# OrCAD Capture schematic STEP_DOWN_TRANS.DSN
size A
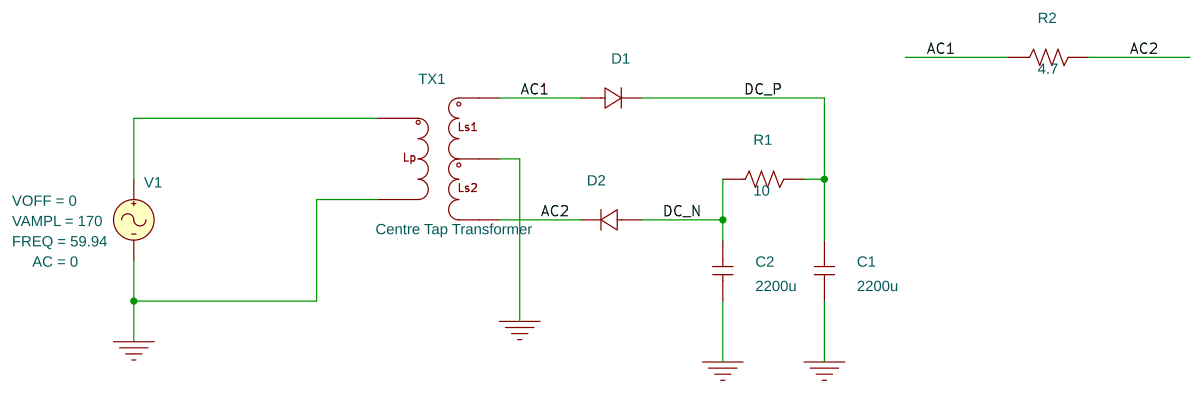
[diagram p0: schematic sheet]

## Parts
C1  2200u  [cap196]
C2  2200u  [cap196]
D1  POWER_DIODE_P
D2  POWER_DIODE_P
R1  10  [AXRC05]
R2  4.7  [AXRC05]
TX1  Centre Tap Transformer
V1  VSIN

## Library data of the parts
C1 C2 = C
D1 D2 = POWER_DIODE_P: CT_ZERO_VOLTS: 300p; I_REV_LEAK: 1e-5; VJ_KNEE: 0.9
R1 R2 = R
TX1 = CETAPS: AppProp: modelname=CETAPS_Model,LP1=1m,RP1=10m,Rs1=10m,N=0.1,LI=100n
V1 = VSIN: AC: 0; FREQ: 59.94; VAMPL: 170; VOFF: 0

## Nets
0: C1.1 C2.1 TX1.1(3) TX1.3(5) V1.2(-)
AC1: D1.0(1) R2.1 TX1.2(4)
AC2: D2.1(2) R2.2 TX1.4(6)
DC_N: C2.2 D2.0(1) R1.1
DC_P: C1.2 D1.1(2) R1.2
N00116: TX1.0(1) V1.1(+)
